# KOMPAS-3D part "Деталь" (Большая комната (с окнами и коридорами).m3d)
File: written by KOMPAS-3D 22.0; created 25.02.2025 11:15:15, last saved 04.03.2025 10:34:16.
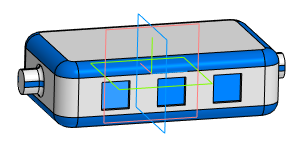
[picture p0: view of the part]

Document properties: Автор: Пользователь Windows; Полное имя файла: C:\Users\Student\Documents\Картошечка\База Сабнатика\Большая комната\Большая комната (с окнами и коридорами).m3d

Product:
- Part/product: Деталь
    Масса: 2.226192

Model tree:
1. Эскиз:1
2. Элемент выдавливания:1
     Расстояние 1 = 35
3. Скругление:2  (with: Элемент выдавливания:1)
     Радиус = 10
4. Скругление:1  (with: Элемент выдавливания:1)
     Радиус = 7
5. Эскиз:2  (with: Элемент выдавливания:1, Скругление:1)
6. Элемент выдавливания:2
     Расстояние 2 = 2
7. Эскиз:3  (with: Элемент выдавливания:1)
8. Элемент выдавливания:3
     Расстояние 1 = 10
9. Скругление:3  (with: Элемент выдавливания:3)
     Радиус = 2
10. Зеркальный массив:1
11. Экземпляр ( 1 )
12. Экземпляр ( 2 )  (with: Элемент выдавливания:2)
13. Зеркальный массив:2  (with: Экземпляр ( 1 ), Экземпляр ( 2 ), Элемент выдавливания:3, Скругление:3)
